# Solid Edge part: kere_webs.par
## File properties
Author: Blackblade
Template: Normal.par
Last saved by: Blackblade
Revision: 26
Application: Solid Edge
Accuracy: 0.990
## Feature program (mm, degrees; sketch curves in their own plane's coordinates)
sketch for "unnamed RevolvedProtrusion 1" plane through (0, 0, 0) normal (0, 0, 1) x-axis (1, 0, 0)
  line (-131.2752, -0.4082) -> (366.9641, -0.4082)
revolve "unnamed RevolvedProtrusion 1" add finite
sketch for "ExtrudedProtrusion_2" plane through (0, 0, 0) normal (1, 0, 0) x-axis (0, 1, 0)
  circle centre (39.1808, -35.3975) radius 14.1815
extrude "ExtrudedProtrusion_2" add finite 98 along -normal
mirror "unnamed Mirror 1" of "ExtrudedProtrusion_2" about plane through (0, 0, 0) normal (0, -1, 0)
extrude "unnamed Protrusion 1" add finite 98
sketch for "ExtrudedCutout_5" plane through (-98, 40.3491, -36.1682) normal (-1, 0, 0) x-axis (0, -1, 0)
  circle centre (1.1683, 0.7706) radius 14.1815
extrude "ExtrudedCutout_5" cut finite 690.3861 along +normal
mirror "unnamed Mirror 2" of "ExtrudedCutout_5" about plane through (0, 0, 0) normal (0, -1, 0)
extrude "unnamed Cutout 1" cut finite 690.3861
sketch for "ExtrudedProtrusion_5" plane through (0, 0, 0) normal (1, 0, 0) x-axis (0, 1, 0)
  line (-2, -71.8367) -> (-2, -41.8367)
  line (-2, -41.8367) -> (2, -41.8367)
  line (2, -41.8367) -> (2, -71.8367)
  line (2, -71.8367) -> (-2, -71.8367)
extrude "ExtrudedProtrusion_5" add finite 203.6684 symmetric
fillet "Round_3" radius 3
fillet "Round_4" radius 1
fillet "Round_5" radius 5
sketch for "voll" plane through (-98, 39.1808, -35.3975) normal (-1, 0, 0) x-axis (0, -1, 0)
  circle centre (0, 0) radius 2.5
extrude "voll" add finite 4 along +normal
mirror "unnamed Mirror 3" of "voll" about plane through (0, 0, 0) normal (0, -1, 0)
extrude "unnamed Protrusion 2" add finite 4
sketch for "ExtrudedProtrusion_9" plane through (117.8445, -0.4082, 0) normal (0, 0, 1) x-axis (-1, 0, 0)
  arc centre (49.919, -577.1273) radius 650 from (234.7252, 46.0474) to (-249.1196, 0) ccw
  arc centre (49.919, 577.1273) radius 650 from (234.7252, -46.0474) to (-249.1196, 0) cw
  arc centre (168.2704, 0) radius 80.8492 from (234.7252, -46.0474) to (234.7252, 46.0474) ccw
extrude "ExtrudedProtrusion_9" add finite 0.1 along +normal
sketch for "ExtrudedCutout_7" plane through (117.8445, -0.4082, 0) normal (0, 0, 1) x-axis (1, 0, 0)
  arc centre (-49.919, 577.1273) radius 649 from (-234.1025, -45.1889) to (246.9397, 0) ccw
  arc centre (-49.919, -577.1273) radius 649 from (-234.1025, 45.1889) to (246.9397, 0) cw
  arc centre (-168.2704, 0) radius 79.8492 from (-234.1025, 45.1889) to (-234.1025, -45.1889) ccw
extrude "ExtrudedCutout_7" cut finite 20 along +normal
thinwall "Thinwall_1"  Thickness = 1 mm
web network "WebNetwork_6"  Thickness = 0.25 mm
web network "WebNetwork_9"  Thickness = 0.25 mm
web network "WebNetwork_14"  Thickness = 0.25 mm
web network "WebNetwork_20"  Thickness = 0.25 mm
web network "WebNetwork_21"  Thickness = 0.25 mm
sketch for "unnamed Protrusion 3" plane through (-80, 0, 0) normal (1, 0, 0) x-axis (0, 1, 0)
  arc centre (-0.4082, 0) radius 46.5572 from (-25.5198, -39.2043) to (25.401, -38.7487) ccw
  arc centre (39.1808, -35.3975) radius 14.1815 from (32.6557, -22.8063) to (25.401, -38.7487) ccw
  line (-32.202, -23.052) -> (32.6557, -22.8063)
  arc centre (-39.1808, -35.3975) radius 14.1815 from (-25.5198, -39.2043) to (-32.202, -23.052) ccw
extrude "unnamed Protrusion 3" add to key point along -normal
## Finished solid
Body 1: solid body, 50 faces, 110 edges, 64 vertices.
  Faces by surface: cylinder 18, plane 17, blend 10, torus 3, sphere 2
  Edges by curve: intersection 48, circle 38, line 22, ellipse 2
Bounding box of the edges (mm; curved faces can reach further): 498.239 x 145.745 x 71.937, from (-131.2752, -73.2809, -71.8368) to (366.9641, 72.4645, 0.1).
Cylindrical faces by radius (mm): R1 x4, R2.5 x2, R14.1815 x4, R46.5572 x2, R79.8492 x1, R80.8492 x1, R649 x2, R650 x2
Toroidal faces (ring radius, tube radius in mm): R-577.1273 r649 x1, R-577.1273 r650 x1, R41.7596 r5 x1
Spherical faces by radius (mm): R79.8492 x1, R80.8492 x1
Planar faces by outward normal: +y 1, +z 4, -x 8, -y 1, -z 1, oblique 2
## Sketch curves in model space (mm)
line (180, -56.6775, -21.0903) -> (180, 55.8611, -21.0903)
line (101.6729, 0, 0.2727) -> (87.109, 0, 58.4783)
arc centre (1.6729, 0, -245.066) radius 315.3388 from (1.6729, 0, 70.2727) through (44.7961, 0, 67.3102) to (87.109, 0, 58.4783)
arc centre (-68.3271, 0, 70.2727) radius 70 from (-68.3271, 0, 0.2727) through (-17.411, 0, 22.2358) to (1.6729, 0, 70.2727)
line (1.6729, 0, 0.2727) -> (-68.3271, 0, 0.2727)
line (1.6729, 0, 0.2727) -> (101.6729, 0, 0.2727)
line (180, -41.5968, -21.2153) -> (180, 41.5968, -21.2153)
line (0, -39.1808, -54.4932) -> (0, -58.5124, -11.9531)
line (0, 39.1808, -54.4932) -> (0, 57.696, -11.9531)
line (-40.6871, 57.4647, -21.2153) -> (-40.6871, -58.2811, -21.2153)
line (-30.0322, 57.696, -11.9531) -> (-30.0322, -58.5124, -11.9531)
line (-30, 44.1891, -12.1152) -> (-30, -45.4477, -12.1152)
line (-80, -39.1808, -54.4932) -> (-80, 39.1808, -54.4932)
line (0, -39.1808, -54.4932) -> (0, 39.1808, -54.4932)
line (23.8239, 0, -42.2937) -> (23.8239, 0, -40.2937)
line (-3.6067, 0, -42.2937) -> (7.0043, 0, -54.3682)
line (19.389, 0, -54.3682) -> (7.0043, 0, -54.3682)
line (19.389, 0, -45.0407) -> (19.389, 0, -54.3682)
line (4.389, 0, -45.0407) -> (19.389, 0, -45.0407)
line (4.389, 0, -30.0407) -> (4.389, 0, -45.0407)
line (-10.611, 0, -30.0407) -> (4.389, 0, -30.0407)
line (-10.611, 0, -15.0407) -> (-10.611, 0, -30.0407)
line (-25.611, 0, -15.0407) -> (-10.611, 0, -15.0407)
line (-25.611, 0, -0.0407) -> (-25.611, 0, -15.0407)
line (-40.611, 0, -0.0407) -> (-25.611, 0, -0.0407)
line (-40.611, 0, -0.0407) -> (-3.6067, 0, -42.2937)
arc centre (67.9255, -577.5355, 0) radius 650 from (-116.8807, 45.6392, 0) through (129.5076, 69.5407, 0) to (366.9641, -0.4082, 0)
arc centre (-50.426, -0.4082, 0) radius 80.8492 from (-116.8807, 45.6392, 0) through (-131.2415, -2.7408, 0) to (-116.8807, -46.4556, 0)
arc centre (67.9255, 576.7191, 0) radius 650 from (-116.8807, -46.4556, 0) through (129.5076, -70.3571, 0) to (366.9641, -0.4082, 0)
arc centre (67.9255, 576.7191, 0) radius 649 from (-116.258, -45.5971, 0) through (128.625, -69.4361, 0) to (364.7842, -0.4082, 0)
arc centre (-50.426, -0.4082, 0) radius 79.8492 from (-116.258, 44.7807, 0) through (-130.2424, -2.6952, 0) to (-116.258, -45.5971, 0)
arc centre (67.9255, -577.5355, 0) radius 649 from (-116.258, 44.7807, 0) through (128.625, 68.6197, 0) to (364.7842, -0.4082, 0)
line (0, -2, -71.8367) -> (0, -2, -41.8367)
line (0, -2, -41.8367) -> (0, 2, -41.8367)
line (0, 2, -41.8367) -> (0, 2, -71.8367)
line (0, 2, -71.8367) -> (0, -2, -71.8367)
line (313.7191, -79.3024, 0) -> (109.0213, -198.7559, 0)
line (431.6887, -212.8529, 0) -> (313.7191, -79.3024, 0)
line (154.2004, -205.4335, 0) -> (431.6887, -212.8529, 0)
line (109.0213, -198.7559, 0) -> (321.1382, -209.897, 0)
line (0, -0.4082, -72.8727) -> (0, -16.0575, -69.8405)
arc centre (0, -15.1063, -64.9318) radius 5 from (0, -19.5742, -67.1764) through (0, -18.1255, -68.9173) to (0, -16.0575, -69.8405)
line (0, -72.9609, -5.669) -> (0, -73.2809, 0)
arc centre (0, -67.9689, -5.3873) radius 5 from (0, -72.9609, -5.669) through (0, -72.3044, -7.8778) to (0, -70.7271, -9.5577)
arc centre (0, -153.2512, -134.3368) radius 149.5997 from (0, -70.7271, -9.5577) through (0, -41.3775, -35.0174) to (0, -19.5742, -67.1764)
arc centre (67.9255, -577.5355, 0) radius 650 from (-116.8807, 45.6392, 0) through (129.5076, 69.5407, 0) to (366.9641, -0.4082, 0)
arc centre (-50.426, -0.4082, 0) radius 80.8492 from (-131.2752, -0.4082, 0) through (-127.5927, 23.7142, 0) to (-116.8807, 45.6392, 0)
line (-131.2752, -0.4082, 0) -> (366.9641, -0.4082, 0)
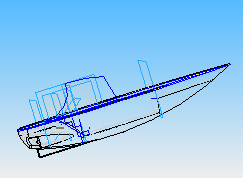
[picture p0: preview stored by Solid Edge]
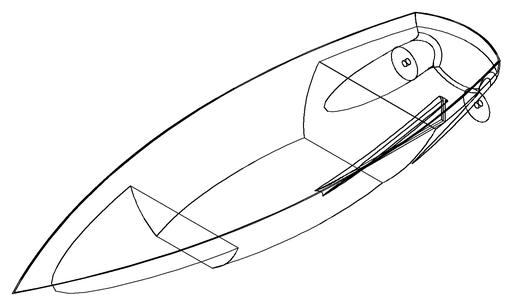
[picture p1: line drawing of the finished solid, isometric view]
